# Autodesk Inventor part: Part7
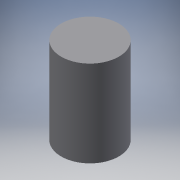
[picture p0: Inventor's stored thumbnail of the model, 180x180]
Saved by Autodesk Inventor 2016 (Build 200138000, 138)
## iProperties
Created: 2020-04
Part Number: Part7
Material: Generic
Document SubType Name: Modeling
Designer: merlin
Density: 1 g/cm^3
Appearance: Default
Author: merlin
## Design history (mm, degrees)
sketch "Sketch1"
  geometry: C1 r 5.08 at (0, 0); 1 further point
  constraints: 1 centre point, 1 coincident
  dimensions: "d0" = 10.16 diameter of C1
extrude "Extrusion1" new body sketch "Sketch1" distance "d1" = 15.24; taper "d2" = 0 deg
body "Solid1"
